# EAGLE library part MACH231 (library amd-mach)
AMD MACH SERIES
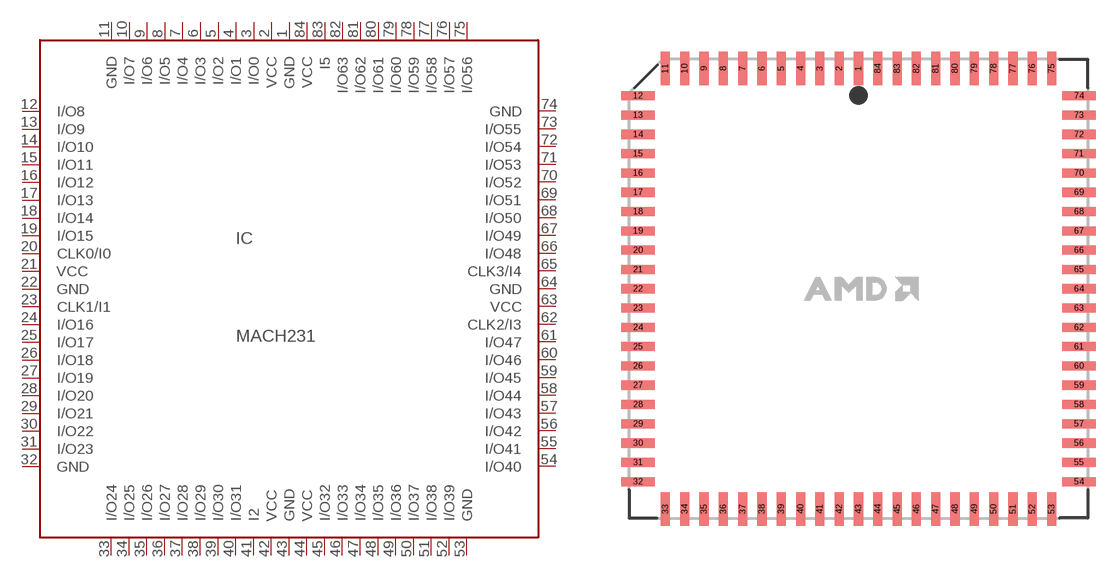
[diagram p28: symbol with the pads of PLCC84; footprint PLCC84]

Designator prefix IC

## MACH231 (OC_FARNELL: unknown; OC_NEWARK: unknown)  [PLCC84]
1  GND  pwr
2  VCC  pwr
3  I/O0
4  I/O1
5  I/O2
6  I/O3
7  I/O4
8  I/O5
9  I/O6
10  I/O7
11  GND  pwr
12  I/O8
13  I/O9
14  I/O10
15  I/O11
16  I/O12
17  I/O13
18  I/O14
19  I/O15
20  CLK0/I0  in
21  VCC  pwr
22  GND  pwr
23  CLK1/I1  in
24  I/O16
25  I/O17
26  I/O18
27  I/O19
28  I/O20
29  I/O21
30  I/O22
31  I/O23
32  GND  pwr
33  I/O24
34  I/O25
35  I/O26
36  I/O27
37  I/O28
38  I/O29
39  I/O30
40  I/O31
41  I2  in
42  VCC  pwr
43  GND  pwr
44  VCC  pwr
45  I/O32
46  I/O33
47  I/O34
48  I/O35
49  I/O36
50  I/O37
51  I/O38
52  I/O39
53  GND  pwr
54  I/O40
55  I/O41
56  I/O42
57  I/O43
58  I/O44
59  I/O45
60  I/O46
61  I/O47
62  CLK2/I3  in
63  VCC  pwr
64  GND  pwr
65  CLK3/I4  in
66  I/O48
67  I/O49
68  I/O50
69  I/O51
70  I/O52
71  I/O53
72  I/O54
73  I/O55
74  GND  pwr
75  I/O56
76  I/O57
77  I/O58
78  I/O59
79  I/O60
80  I/O61
81  I/O62
82  I/O63
83  I5  in
84  VCC  pwr

## Footprint PLCC84 (pad centres in mm)
PLASTIC LEADED CHIP CARRIER
smd 0.6 x 2.2: 1 0,14.5; 2 -1.27,14.5; 3 -2.54,14.5; 4 -3.81,14.5; 5 -5.08,14.5; 6 -6.35,14.5; 7 -7.62,14.5; 8 -8.89,14.5; 9 -10.16,14.5; 10 -11.43,14.5; 11 -12.7,14.5; 33 -12.7,-14.5; 34 -11.43,-14.5; 35 -10.16,-14.5; 36 -8.89,-14.5; 37 -7.62,-14.5; 38 -6.35,-14.5; 39 -5.08,-14.5; 40 -3.81,-14.5; 41 -2.54,-14.5; 42 -1.27,-14.5; 43 0,-14.5; 44 1.27,-14.5; 45 2.54,-14.5; 46 3.81,-14.5; 47 5.08,-14.5; 48 6.35,-14.5; 49 7.62,-14.5; 50 8.89,-14.5; 51 10.16,-14.5; 52 11.43,-14.5; 53 12.7,-14.5; 75 12.7,14.5; 76 11.43,14.5; 77 10.16,14.5; 78 8.89,14.5; 79 7.62,14.5; 80 6.35,14.5; 81 5.08,14.5; 82 3.81,14.5; 83 2.54,14.5; 84 1.27,14.5
smd 2.2 x 0.6: 12 -14.5,12.7; 13 -14.5,11.43; 14 -14.5,10.16; 15 -14.5,8.89; 16 -14.5,7.62; 17 -14.5,6.35; 18 -14.5,5.08; 19 -14.5,3.81; 20 -14.5,2.54; 21 -14.5,1.27; 22 -14.5,0; 23 -14.5,-1.27; 24 -14.5,-2.54; 25 -14.5,-3.81; 26 -14.5,-5.08; 27 -14.5,-6.35; 28 -14.5,-7.62; 29 -14.5,-8.89; 30 -14.5,-10.16; 31 -14.5,-11.43; 32 -14.5,-12.7; 54 14.5,-12.7; 55 14.5,-11.43; 56 14.5,-10.16; 57 14.5,-8.89; 58 14.5,-7.62; 59 14.5,-6.35; 60 14.5,-5.08; 61 14.5,-3.81; 62 14.5,-2.54; 63 14.5,-1.27; 64 14.5,0; 65 14.5,1.27; 66 14.5,2.54; 67 14.5,3.81; 68 14.5,5.08; 69 14.5,6.35; 70 14.5,7.62; 71 14.5,8.89; 72 14.5,10.16; 73 14.5,11.43; 74 14.5,12.7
